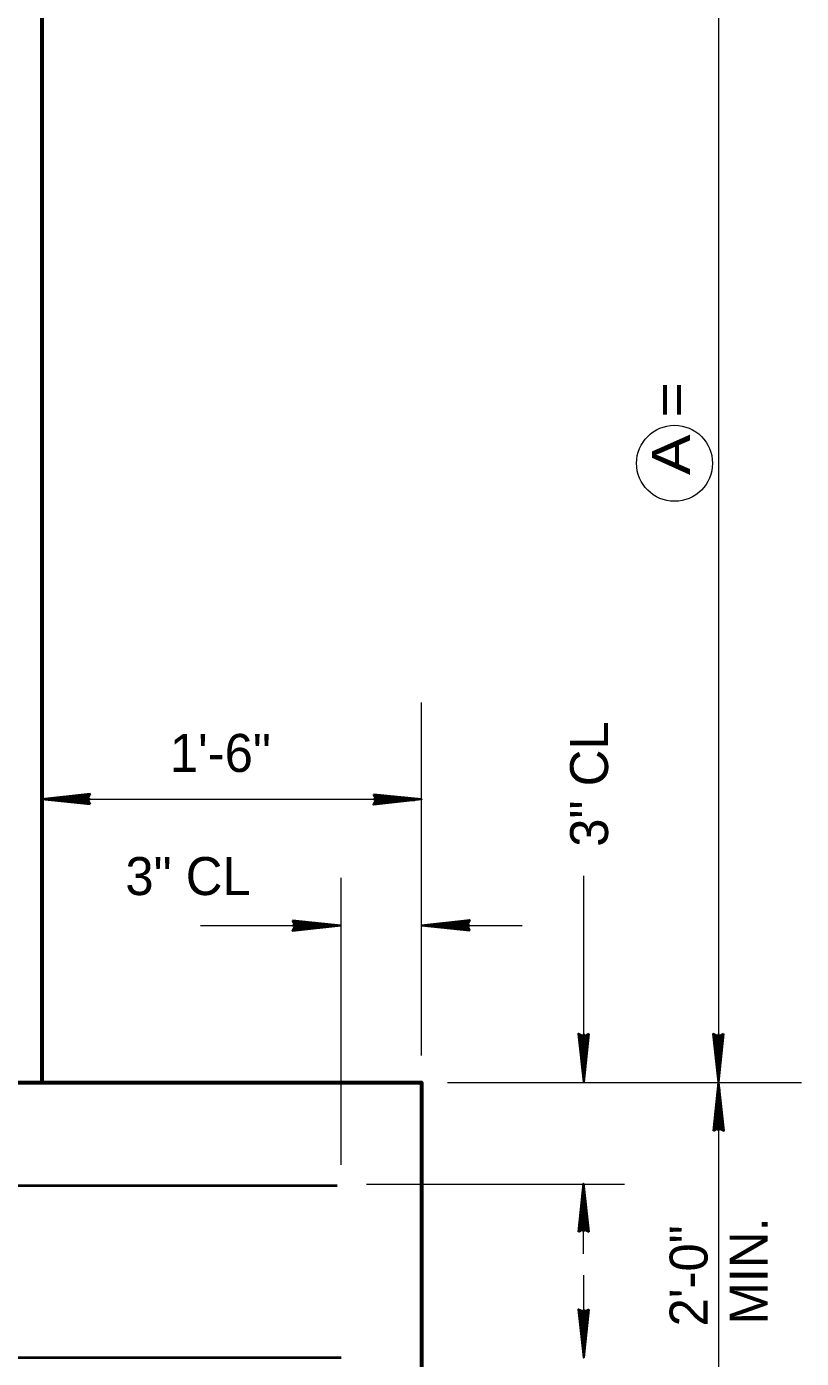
# Model space of a CAD drawing. Extents: x 4.49 to 7.69, y 0.28 to 2.27.
# Drawn here: x 5.4591 to 5.6291, y 0.6219 to 0.9139 of the extents above; entities that cross this region are included whole.
import ezdxf

# ---------------------------------------------------------------- set-up
doc = ezdxf.new("R2010")
doc.units = 0
doc.header["$LTSCALE"] = 0.0033
doc.layers.add('1', color=7, linetype='Continuous', lineweight=35)

msp = doc.modelspace()

# ---------------------------------------------------------------- linework, layer by layer
at = {"layer": '1', "lineweight": 13}
for p, q in [((5.610917, 1.013917), (5.610917, 0.599083)), ((5.54575, 0.688333), (5.54575, 0.76575)), ((5.462417, 0.7445), (5.545333, 0.7445)), ((5.528083, 0.664333), (5.528083, 0.72725)), ((5.581333, 0.692417), (5.581333, 0.72775)), ((5.49725, 0.716833), (5.518083, 0.716833)), ((5.555667, 0.716833), (5.567833, 0.716833)), ((5.551417, 0.682417), (5.629083, 0.682417)), ((5.533667, 0.660083), (5.59025, 0.660083)), ((5.58125, 0.644833), (5.58125, 0.65475)), ((5.581333, 0.630333), (5.581333, 0.640167))]:
    msp.add_line(p, q, dxfattribs=at)
at = {"layer": '1'}
for p, q in [((5.47275, 0.743667), (5.464917, 0.744667)), ((5.47275, 0.745583), (5.465417, 0.74475)), ((5.47275, 0.745417), (5.465417, 0.744667)), ((5.47275, 0.745333), (5.465417, 0.7445)), ((5.472833, 0.745167), (5.4655, 0.744417)), ((5.535417, 0.7455), (5.54325, 0.744583)), ((5.535417, 0.7455), (5.54325, 0.744583)), ((5.535417, 0.745417), (5.54325, 0.744583)), ((5.535417, 0.745333), (5.54325, 0.7445)), ((5.535417, 0.745333), (5.54325, 0.744333)), ((5.473, 0.7445), (5.462417, 0.7445)), ((5.47275, 0.743667), (5.464917, 0.7445)), ((5.47275, 0.7435), (5.464917, 0.744417)), ((5.47275, 0.7435), (5.464917, 0.744417)), ((5.47275, 0.743583), (5.464917, 0.744417)), ((5.535167, 0.7445), (5.54575, 0.7445)), ((5.535333, 0.743833), (5.542667, 0.744583)), ((5.535417, 0.743667), (5.54275, 0.7445)), ((5.535417, 0.743583), (5.54275, 0.744333)), ((5.535417, 0.743417), (5.54275, 0.74425)), ((5.517417, 0.716833), (5.528, 0.716833)), ((5.517583, 0.716167), (5.524917, 0.716917)), ((5.517667, 0.717833), (5.5255, 0.716917)), ((5.517667, 0.717833), (5.5255, 0.716917)), ((5.517667, 0.71775), (5.5255, 0.716917)), ((5.517667, 0.717667), (5.5255, 0.716833)), ((5.517667, 0.717667), (5.5255, 0.716667)), ((5.517667, 0.716), (5.525, 0.716833)), ((5.517667, 0.715917), (5.525, 0.716667)), ((5.517667, 0.71575), (5.525, 0.716583)), ((5.556333, 0.716833), (5.54575, 0.716833)), ((5.556083, 0.716), (5.54825, 0.717)), ((5.556083, 0.716), (5.54825, 0.716833)), ((5.556083, 0.715833), (5.54825, 0.71675)), ((5.556083, 0.715833), (5.54825, 0.71675)), ((5.556083, 0.715917), (5.54825, 0.71675)), ((5.556083, 0.717917), (5.54875, 0.717083)), ((5.556083, 0.71775), (5.54875, 0.717)), ((5.556083, 0.717667), (5.54875, 0.716833)), ((5.556167, 0.7175), (5.548833, 0.71675)), ((5.58025, 0.692833), (5.581083, 0.6855)), ((5.580417, 0.692833), (5.581167, 0.6855)), ((5.5805, 0.692833), (5.581333, 0.6855)), ((5.580667, 0.692917), (5.581417, 0.685583)), ((5.582167, 0.692833), (5.581167, 0.685)), ((5.581333, 0.693083), (5.581333, 0.6825)), ((5.582167, 0.692833), (5.581333, 0.685)), ((5.582333, 0.692833), (5.581417, 0.685)), ((5.582333, 0.692833), (5.581417, 0.685)), ((5.58225, 0.692833), (5.581417, 0.685)), ((5.609833, 0.692833), (5.610667, 0.6855)), ((5.61, 0.692833), (5.61075, 0.6855)), ((5.610083, 0.692833), (5.610917, 0.6855)), ((5.61025, 0.692917), (5.611, 0.685583)), ((5.61175, 0.692833), (5.61075, 0.685)), ((5.610917, 0.693083), (5.610917, 0.6825)), ((5.61175, 0.692833), (5.610917, 0.685)), ((5.611917, 0.692833), (5.611, 0.685)), ((5.611917, 0.692833), (5.611, 0.685)), ((5.611833, 0.692833), (5.611, 0.685)), ((5.610917, 0.671833), (5.610917, 0.682417)), ((5.609917, 0.672083), (5.610833, 0.679917)), ((5.609917, 0.672083), (5.610833, 0.679917)), ((5.61, 0.672083), (5.610833, 0.679917)), ((5.610083, 0.672083), (5.610917, 0.679917)), ((5.610083, 0.672083), (5.611083, 0.679917)), ((5.611583, 0.672), (5.610833, 0.679333)), ((5.61175, 0.672083), (5.610917, 0.679417)), ((5.611833, 0.672083), (5.611083, 0.679417)), ((5.612, 0.672083), (5.611167, 0.679417)), ((5.58125, 0.649667), (5.58125, 0.66025)), ((5.58025, 0.649917), (5.581167, 0.65775)), ((5.58025, 0.649917), (5.581167, 0.65775)), ((5.580333, 0.649917), (5.581167, 0.65775)), ((5.580417, 0.649917), (5.58125, 0.65775)), ((5.580417, 0.649917), (5.581417, 0.65775)), ((5.581917, 0.649833), (5.581167, 0.657167)), ((5.582083, 0.649917), (5.58125, 0.65725)), ((5.582167, 0.649917), (5.581417, 0.65725)), ((5.582333, 0.649917), (5.5815, 0.65725)), ((5.58025, 0.632417), (5.581083, 0.625083)), ((5.580417, 0.632417), (5.581167, 0.625083)), ((5.5805, 0.632417), (5.581333, 0.625083)), ((5.580667, 0.6325), (5.581417, 0.625167)), ((5.582167, 0.632417), (5.581167, 0.624583)), ((5.581333, 0.632667), (5.581333, 0.622083)), ((5.582167, 0.632417), (5.581333, 0.624583)), ((5.582333, 0.632417), (5.581417, 0.624583)), ((5.582333, 0.632417), (5.581417, 0.624583)), ((5.58225, 0.632417), (5.581417, 0.624583))]:
    msp.add_line(p, q, dxfattribs=at)
at = {"layer": '1', "lineweight": 60}
for points in [[(5.462417, 1.01575), (5.462417, 0.682417), (5.54575, 0.682417), (5.54575, 0.599083)], [(4.879083, 0.682417), (5.12225, 0.682417), (5.462417, 0.682417)]]:
    msp.add_lwpolyline(points, dxfattribs=at)
at = {"layer": '1'}
for points in [[(5.473, 0.743417), (5.462417, 0.7445), (5.473, 0.745667), (5.472417, 0.7445)], [(5.47225, 0.744417), (5.467583, 0.744333), (5.467583, 0.744417), (5.4685, 0.744417), (5.47225, 0.744333), (5.46925, 0.74425), (5.472417, 0.744167), (5.470167, 0.744083), (5.472417, 0.744), (5.468917, 0.74425), (5.46425, 0.744417), (5.465167, 0.744667), (5.463917, 0.744667), (5.47225, 0.744667), (5.469833, 0.744833), (5.472417, 0.744833), (5.467083, 0.744417), (5.472417, 0.745083)], [(5.535167, 0.745583), (5.54575, 0.7445), (5.535167, 0.743333), (5.53575, 0.7445)], [(5.535917, 0.744583), (5.540583, 0.744667), (5.540583, 0.744583), (5.539667, 0.744583), (5.535917, 0.744667), (5.538917, 0.74475), (5.53575, 0.744833), (5.538, 0.744917), (5.53575, 0.745), (5.53925, 0.74475), (5.543917, 0.744583), (5.543, 0.744333), (5.54425, 0.744333), (5.535917, 0.744333), (5.538333, 0.744167), (5.53575, 0.744167), (5.541083, 0.744583), (5.53575, 0.743917)], [(5.517417, 0.717917), (5.528, 0.716833), (5.517417, 0.715667), (5.518, 0.716833)], [(5.518167, 0.716917), (5.522833, 0.717), (5.522833, 0.716917), (5.521917, 0.716917), (5.518167, 0.717), (5.521167, 0.717083), (5.518, 0.717167), (5.52025, 0.71725), (5.518, 0.717333), (5.5215, 0.717083), (5.526167, 0.716917), (5.52525, 0.716667), (5.5265, 0.716667), (5.518167, 0.716667), (5.520583, 0.7165), (5.518, 0.7165), (5.523333, 0.716917), (5.518, 0.71625)], [(5.556333, 0.71575), (5.54575, 0.716833), (5.556333, 0.718), (5.55575, 0.716833)], [(5.555583, 0.71675), (5.550917, 0.716667), (5.550917, 0.71675), (5.551833, 0.71675), (5.555583, 0.716667), (5.552583, 0.716583), (5.55575, 0.7165), (5.5535, 0.716417), (5.55575, 0.716333), (5.55225, 0.716583), (5.547583, 0.71675), (5.5485, 0.717), (5.54725, 0.717), (5.555583, 0.717), (5.553167, 0.717167), (5.55575, 0.717167), (5.550417, 0.71675), (5.55575, 0.717417)], [(5.582417, 0.693083), (5.581333, 0.6825), (5.580167, 0.693083), (5.581333, 0.6925)], [(5.581417, 0.692333), (5.5815, 0.687667), (5.581417, 0.687667), (5.581417, 0.688583), (5.5815, 0.692333), (5.581583, 0.689333), (5.581667, 0.6925), (5.58175, 0.69025), (5.581833, 0.6925), (5.581583, 0.689), (5.581417, 0.684333), (5.581167, 0.68525), (5.581167, 0.684), (5.581167, 0.692333), (5.581, 0.689917), (5.581, 0.6925), (5.581417, 0.687167), (5.58075, 0.6925)], [(5.612, 0.693083), (5.610917, 0.6825), (5.60975, 0.693083), (5.610917, 0.6925)], [(5.611, 0.692333), (5.611083, 0.687667), (5.611, 0.687667), (5.611, 0.688583), (5.611083, 0.692333), (5.611167, 0.689333), (5.61125, 0.6925), (5.611333, 0.69025), (5.611417, 0.6925), (5.611167, 0.689), (5.611, 0.684333), (5.61075, 0.68525), (5.61075, 0.684), (5.61075, 0.692333), (5.610583, 0.689917), (5.610583, 0.6925), (5.611, 0.687167), (5.610333, 0.6925)], [(5.609833, 0.671833), (5.610917, 0.682417), (5.612083, 0.671833), (5.610917, 0.672417)], [(5.610833, 0.672583), (5.61075, 0.67725), (5.610833, 0.67725), (5.610833, 0.676333), (5.61075, 0.672583), (5.610667, 0.675583), (5.610583, 0.672417), (5.6105, 0.674667), (5.610417, 0.672417), (5.610667, 0.675917), (5.610833, 0.680583), (5.611083, 0.679667), (5.611083, 0.680917), (5.611083, 0.672583), (5.61125, 0.675), (5.61125, 0.672417), (5.610833, 0.67775), (5.6115, 0.672417)], [(5.580167, 0.649667), (5.58125, 0.66025), (5.582417, 0.649667), (5.58125, 0.65025)], [(5.581167, 0.650417), (5.581083, 0.655083), (5.581167, 0.655083), (5.581167, 0.654167), (5.581083, 0.650417), (5.581, 0.653417), (5.580917, 0.65025), (5.580833, 0.6525), (5.58075, 0.65025), (5.581, 0.65375), (5.581167, 0.658417), (5.581417, 0.6575), (5.581417, 0.65875), (5.581417, 0.650417), (5.581583, 0.652833), (5.581583, 0.65025), (5.581167, 0.655583), (5.581833, 0.65025)], [(5.582417, 0.632667), (5.581333, 0.622083), (5.580167, 0.632667), (5.581333, 0.632083)], [(5.581417, 0.631917), (5.5815, 0.62725), (5.581417, 0.62725), (5.581417, 0.628167), (5.5815, 0.631917), (5.581583, 0.628917), (5.581667, 0.632083), (5.58175, 0.629833), (5.581833, 0.632083), (5.581583, 0.628583), (5.581417, 0.623917), (5.581167, 0.624833), (5.581167, 0.623583), (5.581167, 0.631917), (5.581, 0.6295), (5.581, 0.632083), (5.581417, 0.62675), (5.58075, 0.632083)]]:
    msp.add_lwpolyline(points, close=True, dxfattribs=at)
for points in [[(5.47225, 0.744417), (5.472667, 0.743667), (5.472417, 0.743917), (5.47225, 0.74425), (5.472, 0.744167), (5.472167, 0.743833), (5.472333, 0.744583), (5.4725, 0.745083), (5.47275, 0.7455)], [(5.535917, 0.744583), (5.5355, 0.745333), (5.53575, 0.745083), (5.535917, 0.74475), (5.536167, 0.744833), (5.536, 0.745167), (5.535833, 0.744417), (5.535667, 0.743917), (5.535417, 0.7435)], [(5.518167, 0.716917), (5.51775, 0.717667), (5.518, 0.717417), (5.518167, 0.717083), (5.518417, 0.717167), (5.51825, 0.7175), (5.518083, 0.71675), (5.517917, 0.71625), (5.517667, 0.715833)], [(5.555583, 0.71675), (5.556, 0.716), (5.55575, 0.71625), (5.555583, 0.716583), (5.555333, 0.7165), (5.5555, 0.716167), (5.555667, 0.716917), (5.555833, 0.717417), (5.556083, 0.717833)], [(5.581417, 0.692333), (5.582167, 0.69275), (5.581917, 0.6925), (5.581583, 0.692333), (5.581667, 0.692083), (5.582, 0.69225), (5.58125, 0.692417), (5.58075, 0.692583), (5.580333, 0.692833)], [(5.611, 0.692333), (5.61175, 0.69275), (5.6115, 0.6925), (5.611167, 0.692333), (5.61125, 0.692083), (5.611583, 0.69225), (5.610833, 0.692417), (5.610333, 0.692583), (5.609917, 0.692833)], [(5.610833, 0.672583), (5.610083, 0.672167), (5.610333, 0.672417), (5.610667, 0.672583), (5.610583, 0.672833), (5.61025, 0.672667), (5.611, 0.6725), (5.6115, 0.672333), (5.611917, 0.672083)], [(5.581167, 0.650417), (5.580417, 0.65), (5.580667, 0.65025), (5.581, 0.650417), (5.580917, 0.650667), (5.580583, 0.6505), (5.581333, 0.650333), (5.581833, 0.650167), (5.58225, 0.649917)], [(5.581417, 0.631917), (5.582167, 0.632333), (5.581917, 0.632083), (5.581583, 0.631917), (5.581667, 0.631667), (5.582, 0.631833), (5.58125, 0.632), (5.58075, 0.632167), (5.580333, 0.632417)]]:
    msp.add_lwpolyline(points, dxfattribs=at)
at = {"layer": '1', "lineweight": 40}
for points in [[(5.12225, 0.664), (5.184583, 0.664), (5.191833, 0.659833), (5.52725, 0.659833)], [(5.122333, 0.62625), (5.183917, 0.62625), (5.191167, 0.622083), (5.528083, 0.622083)]]:
    msp.add_lwpolyline(points, dxfattribs=at)
at = {"layer": '1', "lineweight": 13}
msp.add_circle((5.60125, 0.818167), 0.008333, dxfattribs=at)

# ---------------------------------------------------------------- texts
at = {"layer": '1', "width": 1.2}
msp.add_text('A =      ', height=0.008334, rotation=90, dxfattribs=at).set_placement((5.604667, 0.815583))
at = {"layer": '1'}
for s, height, p in [('3" CL', 0.008334, (5.586667, 0.734083)), ('MIN.', 0.008334, (5.621667, 0.629333)), ('2\'-0"', 0.008333, (5.6085, 0.628917))]:
    msp.add_text(s, height=height, rotation=90, dxfattribs=at).set_placement(p)
for s, p in [('1\'-6"', (5.4905, 0.7505)), ('3" CL', (5.48075, 0.7235))]:
    msp.add_text(s, height=0.008334, dxfattribs=at).set_placement(p)

doc.saveas('drawing.dxf')
